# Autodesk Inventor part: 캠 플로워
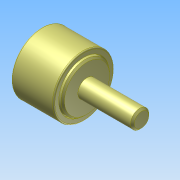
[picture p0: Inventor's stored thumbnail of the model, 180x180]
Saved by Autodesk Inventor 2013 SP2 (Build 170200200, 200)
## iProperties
Created: 2025-09
Part Number: 캠 플로워
Material: Generic
Document SubType Name: Modeling
Designer: a
Density: 1 g/cm^3
Author: a
변환 표준: STEP AP214IS
전처리기: Build: 200, Release: 2013 SP2 Update 6 - Date: Thu 07/17/2014
전송 단위: 밀리미터
불확실성: 0.01
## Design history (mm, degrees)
node "캠 플로워1"
body "Solid1"
node "기준1"
